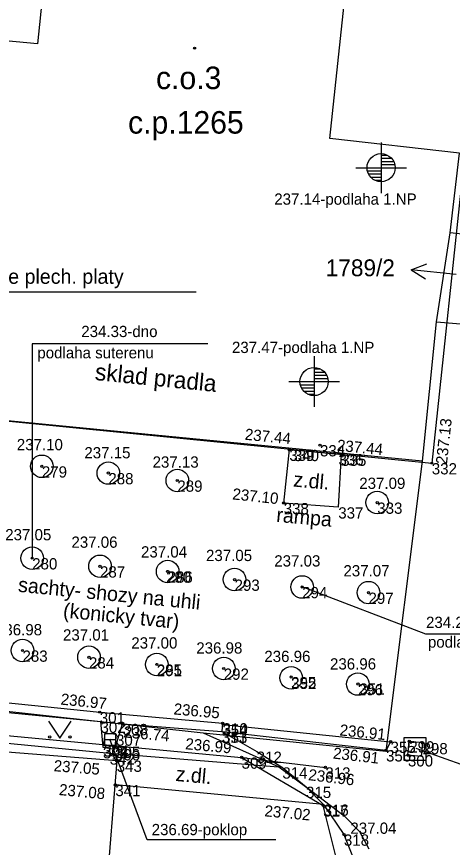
# Model space of a CAD drawing. Extents: x -596309 to -596099, y -1158697 to -1158513.
# Drawn here: x -596228.41 to -596209.08, y -1158676.95 to -1158640.06 of the extents above; entities that cross this region are included whole.
import ezdxf

# ---------------------------------------------------------------- set-up
doc = ezdxf.new("R2010")
doc.units = 0
for name, color, linetype in [('Pop  PČ popisy', 7, 'Continuous'), ('Vrstva 1', 7, 'Continuous'), ('Vrstva 10', 7, 'Continuous'), ('Vrstva 11', 7, 'Continuous'), ('Vrstva 14', 7, 'Continuous'), ('Vrstva 2', 7, 'Continuous'), ('Vrstva 26', 7, 'Continuous'), ('Vrstva 27', 7, 'Continuous'), ('Vrstva 3', 7, 'Continuous'), ('Vrstva 36', 7, 'Continuous'), ('Vrstva 37', 7, 'Continuous'), ('Vrstva 39', 7, 'Continuous'), ('Vrstva 40', 7, 'Continuous'), ('Vrstva 41', 7, 'Continuous'), ('Vrstva 46', 7, 'Continuous'), ('Vrstva 47', 7, 'Continuous'), ('Vrstva 5', 7, 'Continuous'), ('Vrstva 58', 7, 'Continuous'), ('Vrstva 59', 7, 'Continuous'), ('Vrstva 6', 7, 'Continuous'), ('Vrstva 7', 7, 'Continuous'), ('Vrstva 8', 7, 'Continuous'), ('Vrstva 9', 7, 'Continuous')]:
    doc.layers.add(name, color=color, linetype=linetype)

msp = doc.modelspace()

# ---------------------------------------------------------------- linework, layer by layer
at = {"layer": 'Pop  PČ popisy'}
for p, q in [((-596210.91, -1158651.3), (-596210.207, -1158651.036)), ((-596208.91, -1158651.51), (-596210.91, -1158651.3)), ((-596210.91, -1158651.3), (-596210.277, -1158651.704))]:
    msp.add_line(p, q, dxfattribs=at)
at = {"layer": 'Vrstva 1'}
for p, q in [((-596209.78, -1158653.62), (-596209.17, -1158649.66)), ((-596210.4, -1158659.8), (-596235.22, -1158657.39)), ((-596220.14, -1158671.86), (-596216.77, -1158673.37)), ((-596216.77, -1158673.37), (-596215.32, -1158674.46)), ((-596215.32, -1158674.46), (-596213.88, -1158675.55)), ((-596213.88, -1158675.55), (-596213.2, -1158676.25)), ((-596213.2, -1158676.25), (-596212.78, -1158677.02))]:
    msp.add_line(p, q, dxfattribs=at)
for points in [[(-596221.18, -1158580.18), (-596227.49, -1158641.27), (-596233.5, -1158640.71), (-596235.22, -1158657.39), (-596236.63, -1158670.04), (-596220.14, -1158671.86), (-596212.02, -1158672.68), (-596210.4, -1158659.8), (-596209.78, -1158653.62)], [(-596209.17, -1158649.66), (-596208.76, -1158646.12), (-596214.51, -1158645.47), (-596207.66, -1158581.2), (-596207, -1158581.28)], [(-596209.78, -1158653.62), (-596208.18, -1158653.75), (-596204.79, -1158654.07), (-596204.34, -1158654.13), (-596203.99, -1158650.24), (-596204.34, -1158650.19), (-596207.7, -1158649.82), (-596209.17, -1158649.66)]]:
    msp.add_lwpolyline(points, dxfattribs=at)
at = {"layer": 'Vrstva 10'}
msp.add_lwpolyline([(-596234.91, -1158657.42), (-596235.54, -1158663.54), (-596235.64, -1158664.59), (-596236.28, -1158669.77), (-596224.72, -1158670.95), (-596219.27, -1158671.44), (-596219.31, -1158671.81), (-596217.76, -1158672.7), (-596216.62, -1158673.4), (-596215.57, -1158674.26), (-596214.79, -1158675.05), (-596213.89, -1158676.38), (-596213.06, -1158678.46), (-596212.57, -1158681.01), (-596212.72, -1158682.76)], dxfattribs=at)
at = {"layer": 'Vrstva 11'}
for p, q in [((-596219.29, -1158671.81), (-596212.02, -1158672.64)), ((-596214.79, -1158675.05), (-596224.03, -1158674.18))]:
    msp.add_line(p, q, dxfattribs=at)
for points in [[(-596214.01, -1158659.51), (-596214.14, -1158661.85), (-596216.56, -1158661.66), (-596216.31, -1158659.29)], [(-596236.28, -1158669.77), (-596236.52, -1158669.75), (-596236.55, -1158670.21), (-596224.69, -1158671.37), (-596224.58, -1158672.5), (-596224.05, -1158672.59), (-596223.71, -1158671.47), (-596219.31, -1158671.81)], [(-596216.62, -1158673.4), (-596224.28, -1158672.78), (-596234.74, -1158671.76), (-596243.72, -1158670.95)], [(-596219.28, -1158671.49), (-596211.82, -1158672.26), (-596212.02, -1158672.64)]]:
    msp.add_lwpolyline(points, dxfattribs=at)
at = {"layer": 'Vrstva 2'}
for points in [[(-596219.931, -1158654.584), (-596227.727, -1158654.584), (-596227.72, -1158664.11)], [(-596202.68, -1158667.481), (-596210.261, -1158667.481), (-596215.74, -1158665.39)], [(-596216.912, -1158676.611), (-596222.621, -1158676.611), (-596224.272, -1158672.142)], [(-596203.163, -1158673.276), (-596208.688, -1158673.276), (-596210.678, -1158672.56)]]:
    msp.add_lwpolyline(points, dxfattribs=at)
for centre in [(-596214.95, -1158659.09), (-596216.31, -1158659.29), (-596214.01, -1158659.51), (-596209.99, -1158659.89), (-596227.29, -1158660.03), (-596224.34, -1158660.33), (-596221.28, -1158660.66), (-596216.56, -1158661.66), (-596212.41, -1158661.64), (-596227.72, -1158664.11), (-596224.71, -1158664.47), (-596221.71, -1158664.7), (-596218.74, -1158665.06), (-596215.74, -1158665.39), (-596212.8, -1158665.64), (-596228.15, -1158668.21), (-596225.2, -1158668.51), (-596222.19, -1158668.83), (-596219.22, -1158669.01), (-596216.23, -1158669.39), (-596213.27, -1158669.7), (-596224.72, -1158670.95), (-596219.27, -1158671.44), (-596223.71, -1158671.47), (-596224.04, -1158672.48), (-596211.82, -1158672.26), (-596210.99, -1158672.24), (-596210.4, -1158672.32), (-596212.02, -1158672.64), (-596211.05, -1158672.86), (-596223.97, -1158673.1), (-596218.43, -1158672.96), (-596214.71, -1158673.4), (-596224.03, -1158674.18), (-596214.81, -1158675.09), (-596213.89, -1158676.38)]:
    msp.add_circle(centre, 0.05, dxfattribs=at)
at = {"layer": 'Vrstva 26'}
msp.add_lwpolyline([(-596211.237, -1158673.084), (-596210.237, -1158673.084), (-596210.237, -1158672.084), (-596211.237, -1158672.084)], close=True, dxfattribs=at)
at = {"layer": 'Vrstva 27'}
msp.add_line((-596224.51, -1158672.166), (-596224.01, -1158672.166), dxfattribs=at)
msp.add_lwpolyline([(-596224.51, -1158672.416), (-596224.01, -1158672.416), (-596224.01, -1158671.916), (-596224.51, -1158671.916)], close=True, dxfattribs=at)
for centre in [(-596227.29, -1158660.03), (-596224.34, -1158660.33), (-596221.28, -1158660.66), (-596212.41, -1158661.64), (-596227.72, -1158664.11), (-596224.71, -1158664.47), (-596221.71, -1158664.7), (-596218.74, -1158665.06), (-596215.74, -1158665.39), (-596212.8, -1158665.64), (-596228.15, -1158668.21), (-596225.2, -1158668.51), (-596222.19, -1158668.83), (-596219.22, -1158669.01), (-596216.23, -1158669.42), (-596213.27, -1158669.7)]:
    msp.add_circle(centre, 0.5, dxfattribs=at)
at = {"layer": 'Vrstva 3'}
for p, q in [((-596214.95, -1158659.09), (-596214.949, -1158659.09)), ((-596216.31, -1158659.29), (-596216.309, -1158659.29)), ((-596216.11, -1158659.3), (-596216.109, -1158659.3)), ((-596214.13, -1158659.49), (-596214.129, -1158659.49)), ((-596214.01, -1158659.51), (-596214.009, -1158659.51)), ((-596209.99, -1158659.89), (-596209.989, -1158659.89)), ((-596227.29, -1158660.03), (-596227.289, -1158660.03)), ((-596224.34, -1158660.33), (-596224.339, -1158660.33)), ((-596221.28, -1158660.66), (-596221.279, -1158660.66)), ((-596216.56, -1158661.66), (-596216.559, -1158661.66)), ((-596212.41, -1158661.64), (-596212.409, -1158661.64)), ((-596214.14, -1158661.85), (-596214.139, -1158661.85)), ((-596227.72, -1158664.11), (-596227.719, -1158664.11)), ((-596224.71, -1158664.47), (-596224.709, -1158664.47)), ((-596221.78, -1158664.7), (-596221.779, -1158664.7)), ((-596221.71, -1158664.7), (-596221.709, -1158664.7)), ((-596218.74, -1158665.06), (-596218.739, -1158665.06)), ((-596215.74, -1158665.39), (-596215.739, -1158665.39)), ((-596212.8, -1158665.64), (-596212.799, -1158665.64)), ((-596228.15, -1158668.21), (-596228.149, -1158668.21)), ((-596225.2, -1158668.51), (-596225.199, -1158668.51)), ((-596222.19, -1158668.83), (-596222.189, -1158668.83)), ((-596222.19, -1158668.85), (-596222.189, -1158668.85)), ((-596219.22, -1158669.01), (-596219.219, -1158669.01)), ((-596216.23, -1158669.39), (-596216.229, -1158669.39)), ((-596216.23, -1158669.42), (-596216.229, -1158669.42)), ((-596213.27, -1158669.7), (-596213.269, -1158669.7)), ((-596213.2, -1158669.67), (-596213.199, -1158669.67)), ((-596224.72, -1158670.95), (-596224.719, -1158670.95)), ((-596224.69, -1158671.37), (-596224.689, -1158671.37)), ((-596223.71, -1158671.47), (-596223.709, -1158671.47)), ((-596219.28, -1158671.49), (-596219.279, -1158671.49)), ((-596219.27, -1158671.44), (-596219.269, -1158671.44)), ((-596224, -1158671.94), (-596223.999, -1158671.94)), ((-596219.31, -1158671.81), (-596219.309, -1158671.81)), ((-596219.29, -1158671.81), (-596219.289, -1158671.81)), ((-596224.56, -1158672.42), (-596224.559, -1158672.42)), ((-596224.04, -1158672.48), (-596224.039, -1158672.48)), ((-596211.82, -1158672.26), (-596211.819, -1158672.26)), ((-596210.99, -1158672.24), (-596210.989, -1158672.24)), ((-596210.4, -1158672.32), (-596210.399, -1158672.32)), ((-596224.58, -1158672.5), (-596224.579, -1158672.5)), ((-596224.28, -1158672.78), (-596224.279, -1158672.78)), ((-596224.05, -1158672.59), (-596224.049, -1158672.59)), ((-596217.76, -1158672.7), (-596217.759, -1158672.7)), ((-596212.02, -1158672.64), (-596212.019, -1158672.64)), ((-596211.05, -1158672.86), (-596211.049, -1158672.86)), ((-596223.97, -1158673.1), (-596223.969, -1158673.1)), ((-596218.43, -1158672.96), (-596218.429, -1158672.96)), ((-596216.62, -1158673.4), (-596216.619, -1158673.4)), ((-596214.71, -1158673.4), (-596214.709, -1158673.4)), ((-596224.03, -1158674.18), (-596224.029, -1158674.18)), ((-596215.57, -1158674.26), (-596215.569, -1158674.26)), ((-596214.79, -1158675.05), (-596214.789, -1158675.05)), ((-596214.81, -1158675.09), (-596214.809, -1158675.09)), ((-596213.89, -1158676.38), (-596213.889, -1158676.38))]:
    msp.add_line(p, q, dxfattribs=at)
at = {"layer": 'Vrstva 36'}
msp.add_lwpolyline([(-596226.992, -1158671.346), (-596226.492, -1158672.096), (-596225.992, -1158671.346)], dxfattribs=at)
for centre in [(-596226.942, -1158672.046), (-596226.042, -1158672.046)]:
    msp.add_circle(centre, 0.05, dxfattribs=at)
at = {"layer": 'Vrstva 37'}
for p, q in [((-596212.24, -1158645.643), (-596212.24, -1158647.893)), ((-596212.24, -1158645.643), (-596212.24, -1158647.893)), ((-596212.24, -1158646.208), (-596211.962, -1158646.208)), ((-596212.24, -1158646.208), (-596211.962, -1158646.208)), ((-596212.24, -1158646.348), (-596211.777, -1158646.348)), ((-596212.24, -1158646.348), (-596211.777, -1158646.348)), ((-596212.24, -1158646.488), (-596211.681, -1158646.488)), ((-596212.24, -1158646.488), (-596211.681, -1158646.488)), ((-596212.24, -1158646.628), (-596211.631, -1158646.628)), ((-596212.24, -1158646.628), (-596211.631, -1158646.628)), ((-596213.365, -1158646.768), (-596211.115, -1158646.768)), ((-596213.365, -1158646.768), (-596211.115, -1158646.768)), ((-596212.849, -1158646.908), (-596212.24, -1158646.908)), ((-596212.849, -1158646.908), (-596212.24, -1158646.908)), ((-596212.799, -1158647.048), (-596212.24, -1158647.048)), ((-596212.799, -1158647.048), (-596212.24, -1158647.048)), ((-596212.703, -1158647.188), (-596212.24, -1158647.188)), ((-596212.703, -1158647.188), (-596212.24, -1158647.188)), ((-596212.518, -1158647.328), (-596212.24, -1158647.328)), ((-596212.518, -1158647.328), (-596212.24, -1158647.328)), ((-596215.214, -1158655.143), (-596215.214, -1158657.393)), ((-596215.214, -1158655.143), (-596215.214, -1158657.393)), ((-596215.214, -1158655.708), (-596214.936, -1158655.708)), ((-596215.214, -1158655.708), (-596214.936, -1158655.708)), ((-596215.214, -1158655.848), (-596214.751, -1158655.848)), ((-596215.214, -1158655.848), (-596214.751, -1158655.848)), ((-596215.214, -1158655.988), (-596214.655, -1158655.988)), ((-596215.214, -1158655.988), (-596214.655, -1158655.988)), ((-596215.214, -1158656.128), (-596214.605, -1158656.128)), ((-596215.214, -1158656.128), (-596214.605, -1158656.128)), ((-596216.339, -1158656.268), (-596214.089, -1158656.268)), ((-596216.339, -1158656.268), (-596214.089, -1158656.268)), ((-596215.823, -1158656.408), (-596215.214, -1158656.408)), ((-596215.823, -1158656.408), (-596215.214, -1158656.408)), ((-596215.773, -1158656.548), (-596215.214, -1158656.548)), ((-596215.773, -1158656.548), (-596215.214, -1158656.548)), ((-596215.677, -1158656.688), (-596215.214, -1158656.688)), ((-596215.677, -1158656.688), (-596215.214, -1158656.688)), ((-596215.492, -1158656.828), (-596215.214, -1158656.828)), ((-596215.492, -1158656.828), (-596215.214, -1158656.828))]:
    msp.add_line(p, q, dxfattribs=at)
for centre in [(-596212.24, -1158646.768), (-596212.24, -1158646.768), (-596215.214, -1158656.268), (-596215.214, -1158656.268)]:
    msp.add_circle(centre, 0.625, dxfattribs=at)
at = {"layer": 'Vrstva 39'}
for radius in [0.045, 0.0199]:
    msp.add_circle((-596220.512, -1158641.465), radius, dxfattribs=at)
at = {"layer": 'Vrstva 40'}
msp.add_lwpolyline([(-596220.447, -1158652.295), (-596231.373, -1158652.295), (-596237.993, -1158655.304)], dxfattribs=at)
at = {"layer": 'Vrstva 5'}
msp.add_line((-596208.52, -1158646.09), (-596209.99, -1158659.89), dxfattribs=at)
msp.add_lwpolyline([(-596233.37, -1158640.58), (-596235.16, -1158657.39), (-596209.99, -1158659.89)], dxfattribs=at)
msp.add_lwpolyline([(-596234.27, -1158672.28), (-596223.97, -1158673.1), (-596224.452, -1158679.161), (-596234.752, -1158678.341)], close=True, dxfattribs=at)
at = {"layer": 'Vrstva 58'}
for points in [[(-596224.56, -1158672.42), (-596224.04, -1158672.48), (-596223.978, -1158671.943), (-596224.498, -1158671.883)], [(-596211.05, -1158672.86), (-596210.99, -1158672.24), (-596210.398, -1158672.297), (-596210.458, -1158672.917)]]:
    msp.add_lwpolyline(points, close=True, dxfattribs=at)
at = {"layer": 'Vrstva 6'}
msp.add_line((-596216.11, -1158659.3), (-596214.13, -1158659.49), dxfattribs=at)
at = {"layer": 'Vrstva 7'}
msp.add_lwpolyline([(-596278.232, -1158646.344), (-596264.01, -1158641.67), (-596260.07, -1158635.97), (-596256.51, -1158635.49), (-596257.17, -1158642.42), (-596249.77, -1158643.89), (-596245.93, -1158646.05), (-596242.41, -1158660.16), (-596237.69, -1158668.9), (-596235.01, -1158671.41), (-596218.43, -1158672.96), (-596214.81, -1158675.09)], dxfattribs=at)
at = {"layer": 'Vrstva 8'}
msp.add_line((-596213.14, -1158681.73), (-596214.81, -1158675.09), dxfattribs=at)
at = {"layer": 'Vrstva 9'}
msp.add_line((-596218.43, -1158672.96), (-596214.71, -1158673.4), dxfattribs=at)

# ---------------------------------------------------------------- texts
at = {"layer": 'Vrstva 14'}
msp.add_text('1789/2', height=0.75, dxfattribs=at).set_placement((-596214.695, -1158651.59))
at = {"layer": 'Vrstva 2'}
for s, p in [('237.14-podlaha 1.NP', (-596216.98, -1158648.413)), ('234.33-dno', (-596225.542, -1158654.291)), ('podlaha suterenu', (-596227.491, -1158655.236)), ('237.47-podlaha 1.NP', (-596218.857, -1158654.999)), ('237.10', (-596228.403, -1158659.316)), ('237.15', (-596225.403, -1158659.677)), ('237.13', (-596222.378, -1158660.091)), ('237.09', (-596213.209, -1158661.034)), ('237.05', (-596228.916, -1158663.316)), ('237.06', (-596225.978, -1158663.648)), ('237.04', (-596222.892, -1158664.08)), ('237.05', (-596220.007, -1158664.238)), ('237.03', (-596216.98, -1158664.481)), ('237.07', (-596213.91, -1158664.919)), ('234.28-dno', (-596210.246, -1158667.21)), ('236.98', (-596229.326, -1158667.537)), ('237.01', (-596226.353, -1158667.768)), ('237.00', (-596223.322, -1158668.123)), ('podlaha suterenu', (-596210.163, -1158668.083)), ('236.98', (-596220.439, -1158668.346)), ('236.96', (-596217.42, -1158668.722)), ('236.96', (-596214.507, -1158669.055)), ('236.69-poklop', (-596222.418, -1158676.412)), ('237.04', (-596213.602, -1158676.351))]:
    msp.add_text(s, height=0.5, dxfattribs=at).set_placement(p)
for s, rotation, p in [('237.13', 83.9197, (-596209.318, -1158659.962)), ('237.44', 354.3277, (-596218.303, -1158658.849)), ('237.44', 354.3277, (-596214.217, -1158659.336)), ('237.10', 353.9784, (-596218.855, -1158661.498)), ('236.97', 354.1717, (-596226.472, -1158670.61)), ('236.95', 354.8624, (-596221.459, -1158671.047)), ('236.74', 354.8624, (-596223.687, -1158672.067)), ('236.91', 354.107, (-596214.097, -1158671.98)), ('236.99', 354.6592, (-596220.942, -1158672.593)), ('236.91', 353.4869, (-596214.392, -1158673.007)), ('237.05', 355.4482, (-596226.778, -1158673.569)), ('236.96', 353.2544, (-596215.487, -1158673.966)), ('237.08', 354.6211, (-596226.546, -1158674.627)), ('237.02', 354.6211, (-596217.43, -1158675.571))]:
    msp.add_text(s, height=0.5, rotation=rotation, dxfattribs=at).set_placement(p)
at = {"layer": 'Vrstva 40'}
msp.add_text('ocelove plech. platy', height=0.65, dxfattribs=at).set_placement((-596231.295, -1158651.926))
for s, rotation, p in [('z.dl.', 354.8458, (-596216.151, -1158660.927)), ('rampa', 354.8458, (-596216.906, -1158662.495)), ('sachty- shozy na uhli', 354.3277, (-596228.366, -1158665.597)), ('(konicky tvar)', 354.3277, (-596226.368, -1158666.742)), ('z.dl.', 354.8458, (-596221.375, -1158674.002))]:
    msp.add_text(s, height=0.65, rotation=rotation, dxfattribs=at).set_placement(p)
at = {"layer": 'Vrstva 41'}
msp.add_text('sklad pradla', height=0.75, rotation=354.3277, dxfattribs=at).set_placement((-596224.958, -1158656.196))
at = {"layer": 'Vrstva 46'}
msp.add_text('c.o.3', height=1, dxfattribs=at).set_placement((-596222.226, -1158643.28))
at = {"layer": 'Vrstva 47'}
msp.add_text('c.p.1265', height=1, dxfattribs=at).set_placement((-596223.466, -1158645.256))
at = {"layer": 'Vrstva 59'}
for s, p in [('334', (-596214.95, -1158659.59)), ('339', (-596216.31, -1158659.79)), ('340', (-596216.11, -1158659.8)), ('336', (-596214.13, -1158659.99)), ('335', (-596214.01, -1158660.01)), ('332', (-596209.99, -1158660.39)), ('279', (-596227.29, -1158660.53)), ('288', (-596224.34, -1158660.83)), ('289', (-596221.28, -1158661.16)), ('338', (-596216.56, -1158662.16)), ('333', (-596212.41, -1158662.14)), ('337', (-596214.14, -1158662.35)), ('280', (-596227.72, -1158664.61)), ('287', (-596224.71, -1158664.97)), ('290', (-596221.78, -1158665.2)), ('286', (-596221.71, -1158665.2)), ('293', (-596218.74, -1158665.56)), ('294', (-596215.74, -1158665.89)), ('297', (-596212.8, -1158666.14)), ('283', (-596228.15, -1158668.71)), ('284', (-596225.2, -1158669.01)), ('285', (-596222.19, -1158669.33)), ('291', (-596222.19, -1158669.35)), ('292', (-596219.22, -1158669.51)), ('352', (-596216.23, -1158669.92)), ('295', (-596216.23, -1158669.89)), ('296', (-596213.27, -1158670.2)), ('351', (-596213.2, -1158670.17)), ('301', (-596224.72, -1158671.45)), ('302', (-596224.69, -1158671.87)), ('308', (-596223.71, -1158671.97)), ('354', (-596219.28, -1158671.99)), ('310', (-596219.27, -1158671.94)), ('307', (-596224, -1158672.44)), ('311', (-596219.31, -1158672.31)), ('353', (-596219.29, -1158672.31)), ('303', (-596224.58, -1158673)), ('304', (-596224.56, -1158672.92)), ('305', (-596224.04, -1158672.98)), ('355', (-596211.82, -1158672.76)), ('299', (-596210.99, -1158672.74)), ('298', (-596210.4, -1158672.82)), ('342', (-596224.28, -1158673.28)), ('306', (-596224.05, -1158673.09)), ('312', (-596217.76, -1158673.2)), ('356', (-596212.02, -1158673.14)), ('300', (-596211.05, -1158673.36)), ('343', (-596223.97, -1158673.6)), ('309', (-596218.43, -1158673.46)), ('314', (-596216.62, -1158673.9)), ('313', (-596214.71, -1158673.9)), ('341', (-596224.03, -1158674.68)), ('315', (-596215.57, -1158674.76)), ('316', (-596214.79, -1158675.55)), ('317', (-596214.81, -1158675.59)), ('318', (-596213.89, -1158676.88))]:
    msp.add_text(s, height=0.5, dxfattribs=at).set_placement(p)

doc.saveas('drawing.dxf')
